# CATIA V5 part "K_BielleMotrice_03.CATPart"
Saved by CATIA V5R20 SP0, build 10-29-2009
Part number: Bielle_motrice_03
Bounding box of the stored display mesh (mm): x -195 to -75, y -177.303 to -162.303, z 35 to 65
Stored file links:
  G:\Khaled_CFAO_2011\ST2M\ST2M_GR2\jcoetard\Khaled\CAD_CATIA\K_BielleMotrice_03.CATPart
  J:\Thinkmotion\Thinkmotion_COETARD\Maquette_catia\Maquette_catia_R20_Licence_education\jcharlescoetard.CATPRODUCT\Assemblage_Pince_Prehension_Mors_Paralleles.CATProduct
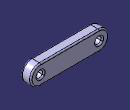
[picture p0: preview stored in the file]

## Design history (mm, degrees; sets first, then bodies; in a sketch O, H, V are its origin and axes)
Set1
  Plane1 "Plan_bielle_motrice_02": linked copy from another document
  Point1: linked copy from another document
  Point2: linked copy from another document
Body1 (main body)
  Sketch1 on Plane1, origin (0, -162.303, 0), H (-1, 0, 0), V (0, 0, 1)
    construction line L1 (90, 50) -> (180, 50)
    point P1 (90, 50)
    point P2 (180, 50)
    line L2 (90, 65) -> (180, 65)
    line L3 (180, 35) -> (90, 35)
    arc A1 centre (180, 50) radius 15 from (180, 65) to (180, 35) cw
    arc A2 centre (90, 50) radius 15 from (90, 35) to (90, 65) cw
    reference projected point E1 (90, 50) from Point1
    reference projected point E2 (180, 50) from Point2
    distance L2 L3 = 30
    tangency: A1 L2, A2 L2, A1 L3, A2 L3
    coincidence: E1 P1, E2 P2
  Pad1: profile Sketch1, direction (0, -1, 0), length 15
  Sketch2 on start face of Pad1, origin (-180, -162.303, 66.6667), H (1, 0, 0), V (0, 0, -1)
    point P1 (0, 16.6667)
    reference projected point E1 (0, 16.6667) from Point2
    coincidence: E1 P1
  Hole1: placed by Sketch2, at (-180, -162.303, 50) direction (0, -1, 0), diameter 10, depth 20
  Sketch3 on start face of Pad1, origin (-90, -162.303, 66.6667), H (1, 0, 0), V (0, 0, -1)
    point P1 (0, 16.6667)
    reference projected point E1 (0, 16.6667) from Point1
    coincidence: E1 P1
  Hole2: placed by Sketch3, at (-90, -162.303, 50) direction (0, -1, 0), diameter 10, depth 20
  Fillet1: radius 2, on end face of Pad1; start face of Pad1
